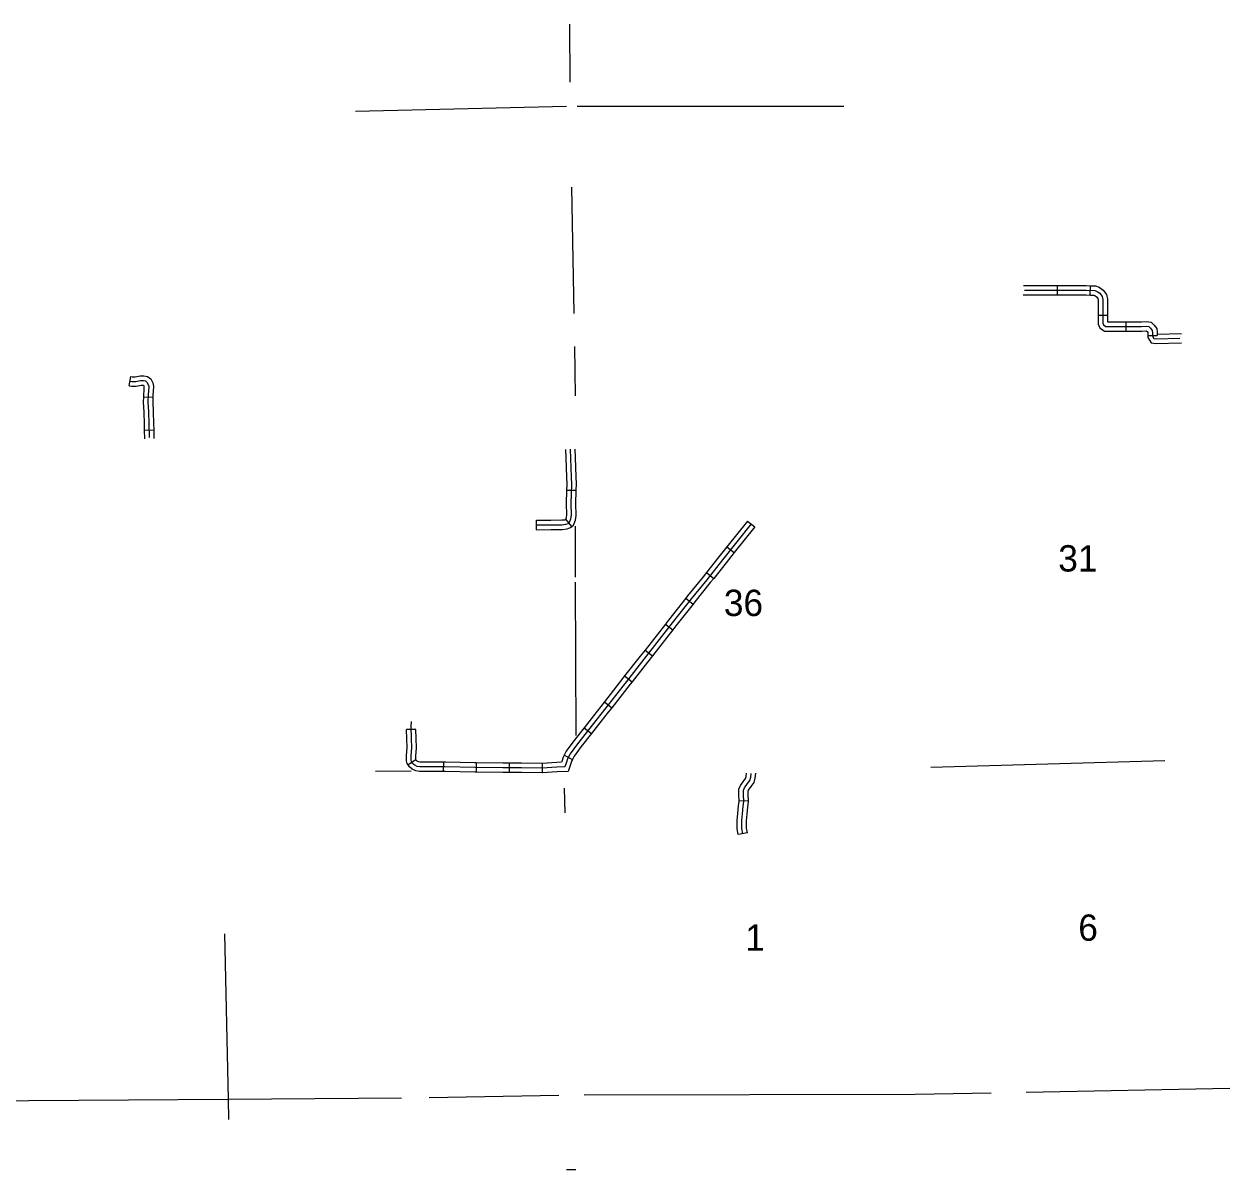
# Model space of a CAD drawing. Extents: x 1127717 to 1741049, y 2026793 to 2244711.
# Drawn here: x 1515445 to 1534772, y 2178159 to 2196528 of the extents above; entities that cross this region are included whole.
import ezdxf

# ---------------------------------------------------------------- set-up
doc = ezdxf.new("R2010")
doc.units = 0
for name, color, linetype in [('32', 7, 'Continuous'), ('4', 7, 'Continuous'), ('5', 7, 'Continuous')]:
    doc.layers.add(name, color=color, linetype=linetype)

msp = doc.modelspace()

# ---------------------------------------------------------------- linework, layer by layer
at = {"layer": '32'}
for p, q in [((1532007, 2192186), (1532007, 2192336)), ((1532532, 2192183), (1532538, 2192333)), ((1532662, 2191863), (1532812, 2191863)), ((1533108, 2191604), (1533108, 2191754)), ((1533458, 2191537), (1533608, 2191537)), ((1517130, 2190728), (1517155, 2190876)), ((1517359, 2190552), (1517509, 2190547)), ((1517372, 2190020), (1517522, 2190023)), ((1524295, 2189050), (1524145, 2189052)), ((1523656, 2188423), (1523656, 2188573)), ((1524223, 2188475), (1524130, 2188593)), ((1527040, 2188561), (1527157, 2188467)), ((1526710, 2188148), (1526827, 2188055)), ((1526381, 2187735), (1526498, 2187642)), ((1526050, 2187323), (1526168, 2187230)), ((1525724, 2186908), (1525842, 2186815)), ((1525398, 2186492), (1525516, 2186400)), ((1525071, 2186078), (1525189, 2185985)), ((1524746, 2185661), (1524865, 2185569)), ((1524420, 2185246), (1524539, 2185154)), ((1521725, 2185219), (1521575, 2185217)), ((1521725, 2184735), (1521601, 2184652)), ((1522165, 2184694), (1522164, 2184544)), ((1522693, 2184683), (1522692, 2184533)), ((1523221, 2184680), (1523221, 2184530)), ((1523750, 2184674), (1523747, 2184524)), ((1524101, 2184809), (1524234, 2184740)), ((1527054, 2184078), (1526904, 2184071)), ((1527039, 2183562), (1526892, 2183536)), ((1524288, 2178159), (1524138, 2178159))]:
    msp.add_line(p, q, dxfattribs=at)
for points in [[(1531462, 2192336), (1532007, 2192336)], [(1531479, 2192261), (1532468, 2192261), (1532605, 2192255), (1532643, 2192244), (1532687, 2192212), (1532726, 2192162), (1532737, 2192113), (1532737, 2191827), (1532737, 2191734), (1532748, 2191706), (1532786, 2191679), (1532973, 2191679), (1533357, 2191679), (1533434, 2191684), (1533473, 2191679), (1533500, 2191651), (1533528, 2191618), (1533533, 2191580), (1533533, 2191525), (1533555, 2191486), (1533588, 2191481), (1533972, 2191492)], [(1532007, 2192336), (1532469, 2192336), (1532538, 2192333)], [(1532538, 2192333), (1532617, 2192330), (1532677, 2192313), (1532740, 2192265), (1532795, 2192195), (1532812, 2192121), (1532812, 2191863)], [(1531459, 2192186), (1532007, 2192186)], [(1532007, 2192186), (1532466, 2192186), (1532532, 2192183)], [(1532532, 2192183), (1532593, 2192181), (1532609, 2192176), (1532634, 2192158), (1532656, 2192129), (1532662, 2192104), (1532662, 2191863)], [(1532662, 2191863), (1532662, 2191827), (1532662, 2191719), (1532686, 2191658), (1532762, 2191604), (1532973, 2191604), (1533108, 2191604)], [(1532812, 2191863), (1532812, 2191827), (1532812, 2191754), (1532973, 2191754), (1533108, 2191754)], [(1533108, 2191754), (1533355, 2191754), (1533437, 2191759), (1533508, 2191749), (1533556, 2191702), (1533599, 2191650), (1533608, 2191585), (1533608, 2191537)], [(1533108, 2191604), (1533360, 2191604), (1533432, 2191609), (1533437, 2191608), (1533445, 2191601), (1533456, 2191586), (1533458, 2191574), (1533458, 2191537)], [(1533458, 2191537), (1533458, 2191505), (1533508, 2191418), (1533583, 2191406), (1533997, 2191417)], [(1533608, 2191556), (1533996, 2191567)], [(1517155, 2190876), (1517175, 2190873), (1517226, 2190874), (1517303, 2190888), (1517367, 2190891), (1517421, 2190878), (1517474, 2190840), (1517507, 2190775), (1517518, 2190726), (1517513, 2190640), (1517510, 2190590), (1517509, 2190547)], [(1517130, 2190728), (1517165, 2190722), (1517242, 2190725), (1517320, 2190739), (1517353, 2190740), (1517357, 2190739), (1517364, 2190724), (1517367, 2190713), (1517363, 2190648), (1517361, 2190596), (1517359, 2190552)], [(1517142, 2190802), (1517170, 2190797), (1517234, 2190800), (1517312, 2190813), (1517360, 2190816), (1517390, 2190809), (1517415, 2190790), (1517436, 2190749), (1517442, 2190719), (1517438, 2190644), (1517436, 2190593), (1517431, 2190465), (1517438, 2190311), (1517445, 2190119), (1517449, 2189898)], [(1517359, 2190552), (1517356, 2190465), (1517363, 2190308), (1517370, 2190117), (1517372, 2190020)], [(1517509, 2190547), (1517506, 2190465), (1517513, 2190314), (1517520, 2190121), (1517522, 2190023)], [(1517372, 2190020), (1517374, 2189880)], [(1517522, 2190023), (1517524, 2189882)], [(1523656, 2188498), (1523664, 2188498), (1523889, 2188500), (1524066, 2188503), (1524130, 2188509), (1524163, 2188524), (1524189, 2188544), (1524211, 2188595), (1524220, 2188656), (1524216, 2188843), (1524222, 2189155), (1524218, 2189267), (1524202, 2189712)], [(1524132, 2189576), (1524127, 2189709)], [(1524282, 2189581), (1524277, 2189714)], [(1524145, 2189052), (1524147, 2189155), (1524143, 2189265), (1524132, 2189576)], [(1524295, 2189050), (1524297, 2189156), (1524293, 2189270), (1524282, 2189581)], [(1524127, 2188591), (1524138, 2188616), (1524145, 2188661), (1524141, 2188843), (1524145, 2189052)], [(1524223, 2188475), (1524250, 2188497), (1524283, 2188574), (1524295, 2188651), (1524291, 2188843), (1524295, 2189050)], [(1523656, 2188573), (1523663, 2188573), (1523888, 2188575), (1524062, 2188578), (1524111, 2188583), (1524124, 2188588), (1524130, 2188593)], [(1527040, 2188561), (1526710, 2188148)], [(1523656, 2188423), (1523664, 2188423), (1523890, 2188425), (1524070, 2188428), (1524149, 2188435), (1524202, 2188459), (1524223, 2188475)], [(1527098, 2188514), (1526639, 2187939), (1526386, 2187621), (1526138, 2187314), (1525834, 2186927), (1525379, 2186347), (1525098, 2185991), (1524748, 2185542), (1524629, 2185391)], [(1527157, 2188467), (1526827, 2188055)], [(1526710, 2188148), (1526580, 2187986), (1526381, 2187735)], [(1526827, 2188055), (1526697, 2187892), (1526498, 2187642)], [(1526381, 2187735), (1526327, 2187668), (1526080, 2187360), (1526050, 2187323)], [(1526498, 2187642), (1526444, 2187574), (1526197, 2187267), (1526168, 2187230)], [(1526050, 2187323), (1525775, 2186973), (1525724, 2186908)], [(1526168, 2187230), (1525893, 2186880), (1525842, 2186815)], [(1525724, 2186908), (1525398, 2186492)], [(1525842, 2186815), (1525516, 2186400)], [(1525398, 2186492), (1525320, 2186393), (1525071, 2186078)], [(1525516, 2186400), (1525438, 2186300), (1525189, 2185985)], [(1525071, 2186078), (1525039, 2186038), (1524746, 2185661)], [(1525189, 2185985), (1525157, 2185945), (1524865, 2185569)], [(1524746, 2185661), (1524689, 2185588), (1524570, 2185438), (1524420, 2185246)], [(1524865, 2185569), (1524807, 2185496), (1524688, 2185345), (1524539, 2185154)], [(1524111, 2184621), (1523986, 2184613), (1523750, 2184599), (1523418, 2184605), (1523117, 2184605), (1522670, 2184608), (1522196, 2184619), (1521789, 2184622), (1521746, 2184628), (1521707, 2184645), (1521678, 2184670), (1521655, 2184704), (1521650, 2184727), (1521650, 2184793), (1521658, 2184929), (1521653, 2185071), (1521650, 2185267), (1521653, 2185347)], [(1524420, 2185246), (1524257, 2185036), (1524133, 2184871), (1524101, 2184809)], [(1524629, 2185391), (1524316, 2184990), (1524197, 2184831), (1524154, 2184748), (1524134, 2184680), (1524111, 2184621)], [(1521601, 2184652), (1521586, 2184674), (1521575, 2184718), (1521575, 2184795), (1521583, 2184930), (1521578, 2185069), (1521575, 2185217)], [(1521725, 2184735), (1521725, 2184735), (1521725, 2184736), (1521725, 2184790), (1521733, 2184928), (1521728, 2185073), (1521725, 2185219)], [(1524539, 2185154), (1524376, 2184945), (1524261, 2184791), (1524234, 2184740)], [(1522164, 2184544), (1521784, 2184547), (1521726, 2184555), (1521666, 2184581), (1521621, 2184621), (1521601, 2184652)], [(1522165, 2184694), (1521794, 2184697), (1521767, 2184701), (1521748, 2184709), (1521735, 2184720), (1521725, 2184735)], [(1522693, 2184683), (1522671, 2184683), (1522197, 2184694), (1522165, 2184694)], [(1523221, 2184680), (1523117, 2184680), (1522693, 2184683)], [(1523750, 2184674), (1523419, 2184680), (1523221, 2184680)], [(1524234, 2184740), (1524224, 2184721), (1524205, 2184656), (1524164, 2184548), (1523991, 2184539), (1523752, 2184524), (1523747, 2184524)], [(1524101, 2184809), (1524084, 2184776), (1524063, 2184704), (1524059, 2184693), (1523982, 2184688), (1523749, 2184674), (1523750, 2184674)], [(1522692, 2184533), (1522669, 2184533), (1522194, 2184544), (1522164, 2184544)], [(1523221, 2184530), (1523116, 2184530), (1522692, 2184533)], [(1523747, 2184524), (1523417, 2184530), (1523221, 2184530)], [(1526904, 2184071), (1526899, 2184175), (1526899, 2184262), (1526926, 2184320), (1526979, 2184395), (1527010, 2184435), (1527017, 2184466), (1527024, 2184518)], [(1526966, 2183549), (1526951, 2183631), (1526951, 2183759), (1526960, 2183867), (1526971, 2183990), (1526980, 2184064), (1526974, 2184177), (1526974, 2184246), (1526991, 2184283), (1527039, 2184351), (1527079, 2184402), (1527091, 2184453), (1527099, 2184516)], [(1527054, 2184078), (1527049, 2184179), (1527049, 2184229), (1527056, 2184245), (1527100, 2184306), (1527149, 2184369), (1527164, 2184440), (1527175, 2184519)], [(1527039, 2183562), (1527026, 2183638), (1527026, 2183756), (1527035, 2183861), (1527046, 2183982), (1527055, 2184061), (1527054, 2184078)], [(1526892, 2183536), (1526876, 2183625), (1526876, 2183762), (1526885, 2183874), (1526897, 2183997), (1526905, 2184066), (1526904, 2184071)]]:
    msp.add_lwpolyline(points, dxfattribs=at)
at = {"layer": '4'}
for points in [[(1529976, 2184613), (1533730, 2184724)], [(1521080, 2184551), (1521648, 2184558)]]:
    msp.add_lwpolyline(points, dxfattribs=at)
at = {"layer": '5'}
for points in [[(1524185, 2196528), (1524192, 2195597)], [(1520758, 2195131), (1524138, 2195212)], [(1524310, 2195214), (1528583, 2195215)], [(1524219, 2193916), (1524256, 2191889)], [(1524266, 2191357), (1524280, 2190570)], [(1524277, 2188479), (1524280, 2187664)], [(1524280, 2187583), (1524290, 2185123)], [(1524103, 2184281), (1524110, 2183881)], [(1518659, 2181941), (1518718, 2179293)], [(1531506, 2179405), (1534772, 2179467)], [(1513116, 2179255), (1518718, 2179293)], [(1518718, 2179293), (1521493, 2179314)], [(1518718, 2179293), (1518724, 2178965)], [(1521937, 2179322), (1524014, 2179357)], [(1524424, 2179360), (1529729, 2179372)], [(1529729, 2179372), (1530945, 2179395)]]:
    msp.add_lwpolyline(points, dxfattribs=at)

# ---------------------------------------------------------------- texts
for s, height, p in [('31', 422.4, (1532021, 2187752)), ('36', 422.4, (1526661, 2187038)), ('6', 422, (1532342, 2181832)), ('1', 422, (1527004, 2181673))]:
    msp.add_text(s, height=height, dxfattribs=at).set_placement(p)

doc.saveas('drawing.dxf')
